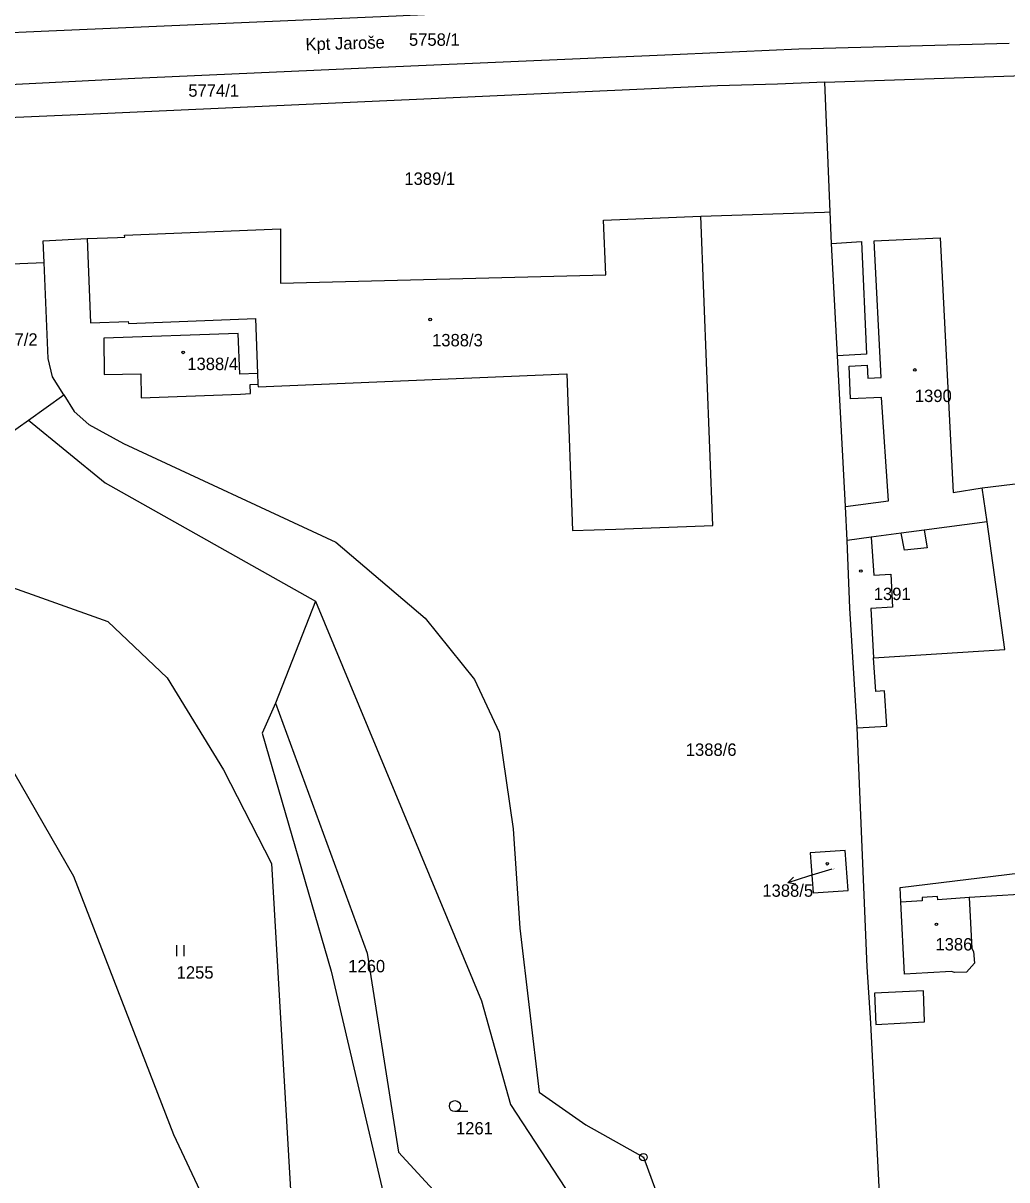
# Model space of a CAD drawing. Extents: x -737240 to -735272, y -1119606 to -1117878.
# Drawn here: x -736182.3 to -736047.5, y -1118993.4 to -1118834.9 of the extents above; entities that cross this region are included whole.
import ezdxf

# ---------------------------------------------------------------- set-up
doc = ezdxf.new("R2010")
doc.units = 0
for name, color, linetype in [('Level 1', 7, 'Continuous'), ('Level 15', 7, 'Continuous'), ('Level 16', 7, 'Continuous'), ('Level 18', 7, 'Continuous'), ('Level 19', 7, 'Continuous'), ('Level 25', 7, 'Continuous'), ('Level 4', 7, 'Continuous')]:
    doc.layers.add(name, color=color, linetype=linetype)

msp = doc.modelspace()

# ---------------------------------------------------------------- linework, layer by layer
at = {"layer": 'Level 1'}
for p, q in [((-736072.43, -1118842.99), (-736045.18, -1118842.06)), ((-736071.7, -1118860.75), (-736072.43, -1118842.99)), ((-736071.52, -1118865.08), (-736071.7, -1118860.75)), ((-736070.71, -1118880.51), (-736071.52, -1118865.08)), ((-736069.62, -1118901.15), (-736070.71, -1118880.51)), ((-736150.18, -1118882.91), (-736150.12, -1118884.35)), ((-736181.57, -1118889.31), (-736176.7, -1118885.84)), ((-736187.03, -1118893.2), (-736181.57, -1118889.31)), ((-736050.22, -1118903.23), (-736050.91, -1118898.59)), ((-736069.38, -1118905.79), (-736069.62, -1118901.15)), ((-736058.84, -1118904.38), (-736061.98, -1118904.8)), ((-736050.22, -1118903.23), (-736058.84, -1118904.38)), ((-736066.12, -1118905.35), (-736069.38, -1118905.79)), ((-736061.98, -1118904.8), (-736066.12, -1118905.35)), ((-736142.25, -1118914.13), (-736147.7, -1118928.07))]:
    msp.add_line(p, q, dxfattribs=at)
for points in [[(-735741.09, -1118934.29), (-735755.85, -1118930.07), (-735760.34, -1118928.26), (-735783.83, -1118919.07), (-735810.33, -1118908.59), (-735869.52, -1118884.9), (-735920.87, -1118865.8), (-735953.25, -1118853.19), (-735997.4, -1118835.89), (-736016.73, -1118829.28), (-736030.6, -1118829.59), (-736086.48, -1118831.76), (-736106.94, -1118832.82), (-736131.16, -1118833.96), (-736155.56, -1118834.99), (-736178.79, -1118836), (-736244.96, -1118838.93), (-736275.1, -1118839.95)], [(-736047.18, -1118837.68), (-736076.02, -1118838.46), (-736092.28, -1118839.21), (-736129.17, -1118840.8), (-736166.98, -1118842.5), (-736185.09, -1118843.38), (-736210.19, -1118844.46), (-736223.5, -1118844.89), (-736245.1, -1118846.15), (-736270.22, -1118847.19), (-736274.85, -1118847.28)], [(-736072.43, -1118842.99), (-736078.92, -1118843.26), (-736087.16, -1118843.5), (-736172.68, -1118847.38), (-736180.08, -1118847.7), (-736207.74, -1118848.86), (-736214.48, -1118849.14), (-736221.42, -1118849.4)], [(-736173.54, -1118864.41), (-736169.38, -1118864.26), (-736168.38, -1118864.22), (-736168.39, -1118863.95), (-736147.01, -1118863.09), (-736147.01, -1118870.55), (-736102.47, -1118869.37), (-736102.78, -1118861.89), (-736089.43, -1118861.33)], [(-736150.12, -1118884.35), (-736150.11, -1118884.75), (-736107.8, -1118882.96), (-736107.03, -1118904.44), (-736101.08, -1118904.25), (-736087.78, -1118903.72), (-736089.43, -1118861.33)], [(-736089.43, -1118861.33), (-736072.51, -1118860.78), (-736071.7, -1118860.75)], [(-736179.42, -1118867.7), (-736179.55, -1118864.71), (-736173.54, -1118864.41)], [(-736173.54, -1118864.41), (-736173.07, -1118875.96), (-736167.88, -1118875.77), (-736167.87, -1118876.04), (-736150.46, -1118875.39), (-736150.18, -1118882.91)], [(-736205.97, -1118868.78), (-736203.99, -1118868.7), (-736179.42, -1118867.7)], [(-736176.7, -1118885.84), (-736178.29, -1118883.38), (-736178.87, -1118880.86), (-736179.42, -1118867.7)], [(-736150.18, -1118882.91), (-736152.62, -1118883), (-736152.81, -1118877.43), (-736171.25, -1118878.08), (-736171.18, -1118883.04), (-736166.15, -1118882.96), (-736166.1, -1118886.23), (-736152.52, -1118885.72), (-736151.13, -1118885.66), (-736151.18, -1118884.41), (-736150.12, -1118884.35)], [(-736176.7, -1118885.84), (-736175.32, -1118888.1), (-736173.31, -1118889.91), (-736168.54, -1118892.5), (-736139.44, -1118906.04), (-736127.19, -1118916.46), (-736120.46, -1118924.83), (-736117.09, -1118932.08), (-736115.17, -1118945.31), (-736114.23, -1118958.93), (-736111.61, -1118981.39), (-736105.2, -1118985.87), (-736097.31, -1118990.31), (-736090.72, -1119008.28), (-736085.91, -1119017.37), (-736080.55, -1119023.47), (-736072.89, -1119029.19), (-736063.09, -1119033.88)], [(-736181.57, -1118889.31), (-736171.06, -1118897.91), (-736142.25, -1118914.13)], [(-736050.91, -1118898.59), (-736043.72, -1118897.72), (-736030.53, -1118896.39)], [(-736197.18, -1118900.44), (-736192.89, -1118908.99), (-736170.67, -1118916.89), (-736162.57, -1118924.63), (-736154.84, -1118937.21), (-736148.26, -1118950.08), (-736145.29, -1119001.08), (-736124.54, -1119034.32), (-736115.2, -1119043.08)], [(-736065.78, -1118921.87), (-736047.81, -1118920.73), (-736050.22, -1118903.23)], [(-736068.04, -1118931.48), (-736069.04, -1118915.09), (-736069.38, -1118905.79)], [(-736142.25, -1118914.13), (-736119.5, -1118968.87), (-736115.51, -1118983.1), (-736106.35, -1118997.1), (-736091.19, -1119018.77), (-736086.44, -1119023.82), (-736095.29, -1119032.63)], [(-736068.04, -1118931.48), (-736063.96, -1118931.22), (-736064.27, -1118926.41), (-736065.45, -1118926.48), (-736065.78, -1118921.87)], [(-736201.48, -1118931.75), (-736189.79, -1118926.86), (-736175.41, -1118951.79), (-736161.67, -1118987.2), (-736142.56, -1119027.91), (-736121.46, -1119052.3), (-736092.38, -1119087.79), (-736091.96, -1119098.89)], [(-736147.7, -1118928.07), (-736149.54, -1118932.21), (-736140.07, -1118964.8), (-736132.65, -1118996.58), (-736107.71, -1119023.78), (-736099.33, -1119035.56)], [(-736147.7, -1118928.07), (-736135.15, -1118962.34), (-736130.84, -1118989.61), (-736104.91, -1119017.81), (-736095.29, -1119032.63)], [(-736063.09, -1119033.88), (-736064.43, -1119006.06), (-736066.17, -1118971.96), (-736066.66, -1118964.2), (-736068.04, -1118931.48)], [(-736074.46, -1118948.62), (-736074.07, -1118954.06), (-736069.26, -1118953.74), (-736069.67, -1118948.28), (-736074.46, -1118948.62)], [(-736062.03, -1118955.35), (-736062.13, -1118953.35), (-736043.78, -1118951.1), (-736042.76, -1118950.68), (-736041.92, -1118949.56), (-736039.46, -1118949.36), (-736038.68, -1118953.63), (-736026.8, -1118958.89)], [(-736052.67, -1118954.74), (-736052.29, -1118961.73), (-736052.07, -1118962.14), (-736051.95, -1118963.72), (-736053.02, -1118964.94), (-736054.67, -1118965.01), (-736055.09, -1118964.84), (-736058.36, -1118965.05), (-736061.54, -1118965.24), (-736062.03, -1118955.35)], [(-736027.07, -1118960.49), (-736038.74, -1118955.48), (-736042.16, -1118956.17), (-736042.04, -1118954.09), (-736052.67, -1118954.74)]]:
    msp.add_lwpolyline(points, dxfattribs=at)
at = {"layer": 'Level 16'}
for points in [[(-736071.51, -1118950.85), (-736074.67, -1118951.82), (-736077.537, -1118952.703)], [(-736076.434, -1118952.886), (-736077.537, -1118952.703), (-736076.729, -1118951.931)]]:
    msp.add_lwpolyline(points, dxfattribs=at)
at = {"layer": 'Level 25'}
for p, q in [((-736161.257, -1118961.245), (-736161.257, -1118962.745)), ((-736160.235, -1118962.745), (-736160.235, -1118961.245)), ((-736121.348, -1118984.07), (-736123.13, -1118984.07))]:
    msp.add_line(p, q, dxfattribs=at)
for centre, major_axis, ratio in [((-736126.53, -1118875.5), (0.18, 0), 0.9848078), ((-736160.36, -1118880.02), (0.18, 0), 0.9848078), ((-736060.13, -1118882.42), (0.18, 0), 0.9848078), ((-736067.52, -1118909.98), (0.18, 0), 0.9848078), ((-736072.11, -1118950.09), (0.18, 0), 0.9848078), ((-736057.17, -1118958.4), (0.18, 0), 0.9848078), ((-736123.13, -1118983.314), (0.764, 0), 0.9894236), ((-736097.31, -1118990.31), (0.516, 0), 0.9848078), ((-736097.31, -1118990.31), (0.0375, 0), 0.9848078)]:
    msp.add_ellipse(centre, major_axis=major_axis, ratio=ratio, dxfattribs=at)
at = {"layer": 'Level 4'}
for points in [[(-736071.52, -1118865.08), (-736067.43, -1118864.84), (-736066.73, -1118880.26), (-736070.71, -1118880.51)], [(-736069.62, -1118901.15), (-736063.73, -1118900.38), (-736064.69, -1118886.19), (-736068.94, -1118886.36), (-736069.12, -1118881.91), (-736066.64, -1118881.79), (-736066.55, -1118883.53), (-736064.72, -1118883.46), (-736065.69, -1118864.74), (-736056.66, -1118864.32), (-736054.89, -1118899.23), (-736050.91, -1118898.59)], [(-736058.84, -1118904.38), (-736058.45, -1118906.81), (-736061.55, -1118907.14), (-736061.98, -1118904.8)], [(-736066.12, -1118905.35), (-736065.76, -1118910.54), (-736063.39, -1118910.43), (-736063.19, -1118914.94), (-736066.15, -1118915.12), (-736065.78, -1118921.87)], [(-736052.67, -1118954.74), (-736056.98, -1118955.02), (-736057, -1118954.58), (-736059.13, -1118954.72), (-736059.1, -1118955.16), (-736062.03, -1118955.35)], [(-736058.78, -1118971.77), (-736058.95, -1118967.49), (-736065.63, -1118967.85), (-736065.45, -1118972.13), (-736058.78, -1118971.77)]]:
    msp.add_lwpolyline(points, dxfattribs=at)

# ---------------------------------------------------------------- texts
at = {"layer": 'Level 15'}
msp.add_text('Kpt Jaroše', height=1.7, rotation=1.50669, dxfattribs=at).set_placement((-736143.587, -1118838.637))
at = {"layer": 'Level 16'}
msp.add_text('1388/5', height=1.7, dxfattribs=at).set_placement((-736081.01, -1118954.62))
at = {"layer": 'Level 18'}
for s, p in [('5758/1', (-736129.43, -1118838)), ('5774/1', (-736159.66, -1118844.98)), ('1389/1', (-736130.06, -1118857.06)), ('1257/2', (-736187.26, -1118879.1)), ('1388/6', (-736091.5, -1118935.31)), ('1255', (-736161.26, -1118965.84)), ('1260', (-736137.75, -1118964.98)), ('1261', (-736122.99, -1118987.19))]:
    msp.add_text(s, height=1.7, dxfattribs=at).set_placement(p)
at = {"layer": 'Level 19'}
for s, height, p in [('1388/3', 1.7, (-736126.26, -1118879.19)), ('1388/4', 1.7, (-736159.8, -1118882.44)), ('1390', 1.7, (-736060.115, -1118886.82)), ('1391', 1.7, (-736065.745, -1118913.96)), ('1388/5', 0.1, (-736071.51, -1118950.85)), ('1386', 1.7, (-736057.295, -1118961.98))]:
    msp.add_text(s, height=height, dxfattribs=at).set_placement(p)

doc.saveas('drawing.dxf')
